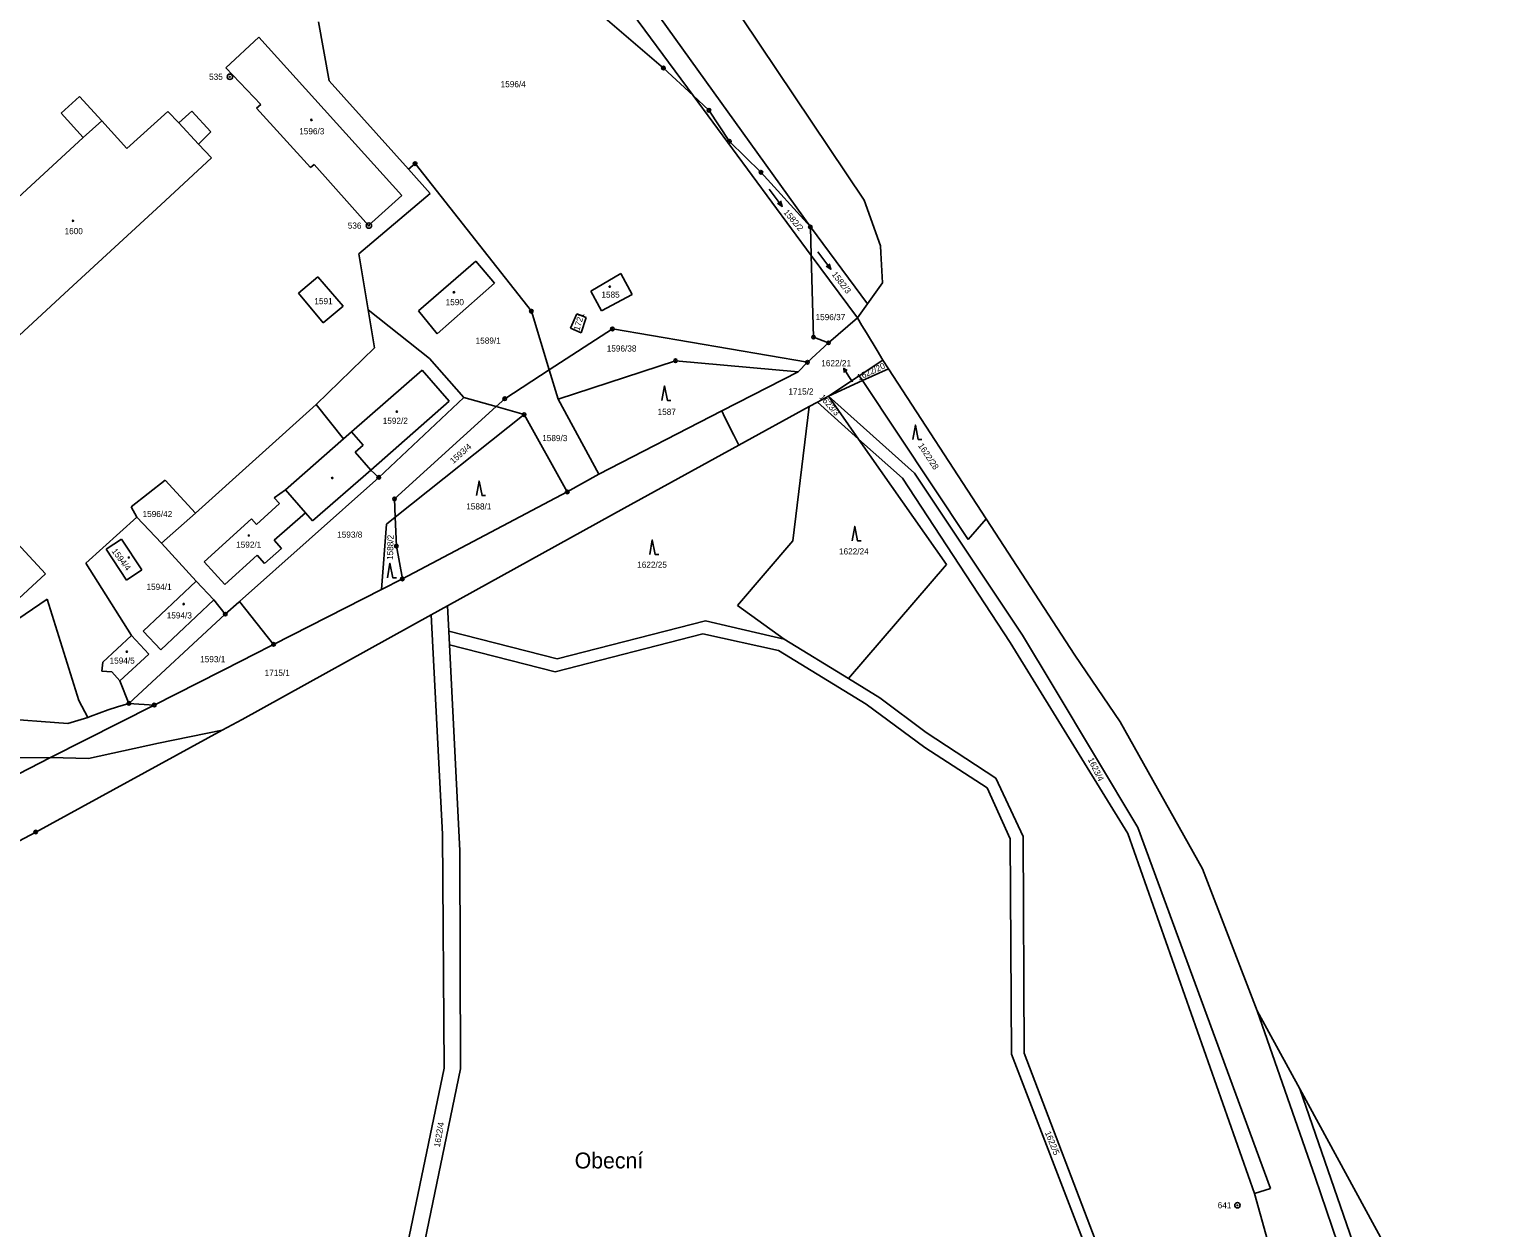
# Model space of a CAD drawing. Extents: x -763296 to -761805, y -1153670 to -1152034.
# Drawn here: x -762319 to -761910.4, y -1153075 to -1152743.4 of the extents above; entities that cross this region are included whole.
import ezdxf

# ---------------------------------------------------------------- set-up
doc = ezdxf.new("R2010")
doc.units = 0
for name, color, linetype in [('Vrstva 1', 7, 'Continuous'), ('Vrstva 13', 7, 'Continuous'), ('Vrstva 15', 7, 'Continuous'), ('Vrstva 16', 7, 'Continuous'), ('Vrstva 17', 7, 'Continuous'), ('Vrstva 18', 7, 'Continuous'), ('Vrstva 19', 7, 'Continuous'), ('Vrstva 24', 7, 'Continuous'), ('Vrstva 25', 7, 'Continuous'), ('Vrstva 4', 7, 'Continuous'), ('Vrstva 6', 7, 'Continuous')]:
    doc.layers.add(name, color=color, linetype=linetype)

msp = doc.modelspace()

# ---------------------------------------------------------------- linework, layer by layer
at = {"layer": 'Vrstva 1'}
for p, q in [((-762153.61, -1152727.41), (-762102.96, -1152798.06)), ((-762158.28, -1152730.66), (-762135.37, -1152761.7)), ((-762159.73, -1152740.22), (-762143.61, -1152754.05)), ((-762239.03, -1152741.3), (-762236.07, -1152757.56)), ((-762264.7, -1152753.98), (-762255.56, -1152745.49)), ((-762255.56, -1152745.49), (-762216.02, -1152789.32)), ((-762255.03, -1152764.19), (-762264.7, -1152753.98)), ((-762236.07, -1152757.56), (-762214.17, -1152782.08)), ((-762143.61, -1152754.05), (-762135.37, -1152761.7)), ((-762135.37, -1152761.7), (-762102.74, -1152805.92)), ((-762135.37, -1152761.7), (-762131.02, -1152765.74)), ((-762310.21, -1152766.54), (-762305.16, -1152761.92)), ((-762305.16, -1152761.92), (-762299.02, -1152768.64)), ((-762256.22, -1152765.2), (-762255.03, -1152764.19)), ((-762241.3, -1152781.61), (-762256.22, -1152765.2)), ((-762131.02, -1152765.74), (-762125.33, -1152774.37)), ((-762304.18, -1152773.27), (-762310.21, -1152766.54)), ((-762299.02, -1152768.64), (-762292.11, -1152776.34)), ((-762292.11, -1152776.34), (-762280.72, -1152766.12)), ((-762280.72, -1152766.12), (-762277.7, -1152769.18)), ((-762274.95, -1152766.7), (-762277.7, -1152769.18)), ((-762274.13, -1152765.96), (-762274.95, -1152766.7)), ((-762268.82, -1152771.72), (-762274.13, -1152765.96)), ((-762323.47, -1152791.06), (-762304.18, -1152773.27)), ((-762268.82, -1152771.72), (-762272.27, -1152775.13)), ((-762272.27, -1152775.13), (-762268.68, -1152778.96)), ((-762125.33, -1152774.37), (-762116.63, -1152782.92)), ((-762282.7, -1152791.88), (-762268.68, -1152778.96)), ((-762240.27, -1152780.76), (-762241.3, -1152781.61)), ((-762225.25, -1152797.65), (-762240.27, -1152780.76)), ((-762212.32, -1152780.52), (-762214.17, -1152782.08)), ((-762214.17, -1152782.08), (-762208.16, -1152788.81)), ((-762212.32, -1152780.52), (-762180.16, -1152821.37)), ((-762116.63, -1152782.92), (-762102.96, -1152798.06)), ((-762208.16, -1152788.81), (-762227.91, -1152805.52)), ((-762216.02, -1152789.32), (-762225.25, -1152797.65)), ((-762308.09, -1152815.37), (-762282.7, -1152791.88)), ((-762102.96, -1152798.06), (-762087.16, -1152819.32)), ((-762102.96, -1152798.06), (-762102.74, -1152805.92)), ((-762227.91, -1152805.52), (-762225.32, -1152820.97)), ((-762102.74, -1152805.92), (-762089.96, -1152823.23)), ((-762102.74, -1152805.92), (-762102.09, -1152828.56)), ((-762211.4, -1152821.24), (-762195.55, -1152807.54)), ((-762195.55, -1152807.54), (-762190.33, -1152813.6)), ((-762244.61, -1152816.37), (-762239.21, -1152811.85)), ((-762239.21, -1152811.85), (-762232.21, -1152820)), ((-762190.33, -1152813.6), (-762206.22, -1152827.59)), ((-762163.73, -1152815.82), (-762155.4, -1152810.91)), ((-762155.4, -1152810.91), (-762152.22, -1152816.74)), ((-762333.07, -1152838.41), (-762308.09, -1152815.37)), ((-762237.74, -1152824.61), (-762244.61, -1152816.37)), ((-762160.74, -1152821.29), (-762163.73, -1152815.82)), ((-762152.22, -1152816.74), (-762160.74, -1152821.29)), ((-762232.21, -1152820), (-762237.74, -1152824.61)), ((-762225.32, -1152820.97), (-762223.54, -1152831.54)), ((-762225.32, -1152820.97), (-762208.31, -1152834.45)), ((-762206.22, -1152827.59), (-762211.4, -1152821.24)), ((-762180.16, -1152821.37), (-762175.2, -1152837.62)), ((-762169.33, -1152826.08), (-762167.59, -1152822.14)), ((-762167.59, -1152822.14), (-762165.03, -1152823.1)), ((-762157.73, -1152826.28), (-762175.2, -1152837.62)), ((-762166.37, -1152827.34), (-762169.33, -1152826.08)), ((-762165.03, -1152823.1), (-762166.37, -1152827.34)), ((-762103.76, -1152835.51), (-762157.73, -1152826.28)), ((-762097.94, -1152830.12), (-762089.96, -1152823.23)), ((-762097.94, -1152830.12), (-762103.76, -1152835.51)), ((-762102.09, -1152828.56), (-762097.94, -1152830.12)), ((-762223.54, -1152831.54), (-762239.65, -1152847.2)), ((-762208.31, -1152834.45), (-762198.88, -1152845.22)), ((-762172.73, -1152845.71), (-762140.27, -1152835.1)), ((-762140.27, -1152835.1), (-762106.32, -1152838.12)), ((-762089.43, -1152839.22), (-762082.89, -1152834.96)), ((-762175.2, -1152837.62), (-762187.52, -1152845.62)), ((-762175.2, -1152837.62), (-762172.73, -1152845.71)), ((-762106.32, -1152838.12), (-762127.49, -1152848.96)), ((-762106.32, -1152838.12), (-762103.76, -1152835.51)), ((-762097.92, -1152844.88), (-762089.43, -1152839.22)), ((-762089.43, -1152839.22), (-762088.51, -1152840.59)), ((-762088.51, -1152840.59), (-762081.34, -1152837.33)), ((-762097.92, -1152844.88), (-762088.51, -1152840.59)), ((-762239.65, -1152847.2), (-762273.08, -1152877.27)), ((-762232.09, -1152856.7), (-762239.65, -1152847.2)), ((-762222.38, -1152867.36), (-762198.88, -1152845.22)), ((-762189.89, -1152847.78), (-762198.88, -1152845.22)), ((-762187.52, -1152845.62), (-762189.89, -1152847.78)), ((-762172.73, -1152845.71), (-762161.45, -1152866.45)), ((-762103.25, -1152847.78), (-762101.01, -1152846.56)), ((-762101.01, -1152846.56), (-762097.92, -1152844.88)), ((-762089.61, -1152856.76), (-762101.01, -1152846.56)), ((-762074.14, -1152866.25), (-762097.92, -1152844.88)), ((-762189.89, -1152847.78), (-762218.02, -1152873.34)), ((-762182.15, -1152849.98), (-762217.82, -1152878.43)), ((-762182.15, -1152849.98), (-762189.89, -1152847.78)), ((-762170.21, -1152871.4), (-762182.15, -1152849.98)), ((-762161.45, -1152866.45), (-762127.49, -1152848.96)), ((-762127.49, -1152848.96), (-762126.58, -1152850.78)), ((-762126.58, -1152850.78), (-762124.13, -1152855.66)), ((-762122.76, -1152858.41), (-762103.25, -1152847.78)), ((-762232.09, -1152856.7), (-762229.91, -1152854.79)), ((-762229.91, -1152854.79), (-762226.66, -1152858.5)), ((-762124.13, -1152855.66), (-762122.76, -1152858.41)), ((-762226.66, -1152858.5), (-762228.92, -1152860.41)), ((-762122.76, -1152858.41), (-762154.45, -1152875.89)), ((-762077.49, -1152867.6), (-762089.61, -1152856.76)), ((-762228.92, -1152860.41), (-762224.6, -1152865.34)), ((-762222.38, -1152867.36), (-762260.93, -1152901.73)), ((-762224.6, -1152865.34), (-762222.38, -1152867.36)), ((-762161.45, -1152866.45), (-762170.21, -1152871.4)), ((-762077.49, -1152867.6), (-762047.66, -1152913.09)), ((-762074.14, -1152866.25), (-762044.29, -1152911.05)), ((-762281.47, -1152868.16), (-762290.91, -1152875.48)), ((-762273.08, -1152877.27), (-762281.47, -1152868.16)), ((-762215.84, -1152895.47), (-762170.21, -1152871.4)), ((-762290.91, -1152875.48), (-762289.28, -1152878.4)), ((-762218.02, -1152873.34), (-762217.82, -1152878.43)), ((-762203.35, -1152902.95), (-762154.45, -1152875.89)), ((-762329.04, -1152878.48), (-762314.62, -1152894.05)), ((-762289.28, -1152878.4), (-762303.44, -1152891.15)), ((-762282.5, -1152885.56), (-762289.28, -1152878.4)), ((-762273.08, -1152877.27), (-762282.5, -1152885.56)), ((-762217.82, -1152878.43), (-762220.23, -1152880.35)), ((-762217.82, -1152878.43), (-762217.51, -1152886.39)), ((-762220.23, -1152880.35), (-762221.58, -1152898.39)), ((-762297.84, -1152887.22), (-762293.59, -1152884.52)), ((-762292.2, -1152895.79), (-762297.84, -1152887.22)), ((-762293.59, -1152884.52), (-762287.93, -1152892.99)), ((-762282.5, -1152885.56), (-762272.88, -1152896.12)), ((-762217.51, -1152886.39), (-762215.84, -1152895.47)), ((-762303.44, -1152891.15), (-762290.78, -1152911.18)), ((-762314.62, -1152894.05), (-762328.32, -1152906.75)), ((-762287.93, -1152892.99), (-762292.2, -1152895.79)), ((-762287.53, -1152909.96), (-762272.88, -1152896.12)), ((-762272.88, -1152896.12), (-762268.04, -1152901.24)), ((-762215.84, -1152895.47), (-762221.58, -1152898.39)), ((-762251.48, -1152913.6), (-762221.58, -1152898.39)), ((-762342.77, -1152920.57), (-762314.13, -1152901.12)), ((-762314.13, -1152901.12), (-762305.37, -1152929.14)), ((-762268.04, -1152901.24), (-762282.68, -1152915.08)), ((-762264.86, -1152905.24), (-762268.04, -1152901.24)), ((-762261.13, -1152901.91), (-762264.86, -1152905.24)), ((-762260.93, -1152901.73), (-762261.13, -1152901.91)), ((-762260.93, -1152901.73), (-762251.48, -1152913.6)), ((-762207.88, -1152905.46), (-762203.35, -1152902.95)), ((-762202.98, -1152909.99), (-762203.35, -1152902.95)), ((-762291.5, -1152929.93), (-762264.86, -1152905.24)), ((-762260.21, -1152934.42), (-762207.88, -1152905.46)), ((-762204.72, -1152966.18), (-762207.88, -1152905.46)), ((-762132.01, -1152907.12), (-762173.02, -1152917.64)), ((-762132.01, -1152907.12), (-762124.89, -1152908.75)), ((-762124.89, -1152908.75), (-762110.17, -1152912.13)), ((-762290.78, -1152911.18), (-762298.73, -1152918.51)), ((-762290.78, -1152911.18), (-762286.03, -1152916.33)), ((-762282.68, -1152915.08), (-762287.53, -1152909.96)), ((-762173.02, -1152917.64), (-762202.98, -1152909.99)), ((-762202.78, -1152913.76), (-762202.98, -1152909.99)), ((-762132.7, -1152910.67), (-762173.56, -1152921.2)), ((-762111.82, -1152915.34), (-762132.7, -1152910.67)), ((-762110.17, -1152912.13), (-762092.41, -1152923.08)), ((-762044.29, -1152911.05), (-762035.82, -1152925.17)), ((-762286.03, -1152916.33), (-762293.98, -1152923.65)), ((-762257.31, -1152916.57), (-762260, -1152917.94)), ((-762257.31, -1152916.57), (-762251.48, -1152913.6)), ((-762173.56, -1152921.2), (-762202.78, -1152913.76)), ((-762199.93, -1152970.65), (-762202.78, -1152913.76)), ((-762087.5, -1152930.15), (-762111.82, -1152915.34)), ((-762047.66, -1152913.09), (-762015.15, -1152965.96)), ((-762298.73, -1152918.51), (-762298.97, -1152921)), ((-762296.25, -1152921.19), (-762298.97, -1152921)), ((-762260, -1152917.94), (-762284.5, -1152930.4)), ((-762293.98, -1152923.65), (-762296.25, -1152921.19)), ((-762291.5, -1152929.93), (-762293.98, -1152923.65)), ((-762092.41, -1152923.08), (-762083.78, -1152928.41)), ((-762035.82, -1152925.17), (-762012.33, -1152964.32)), ((-762305.37, -1152929.14), (-762302.89, -1152933.84)), ((-762083.78, -1152928.41), (-762070.89, -1152937.95)), ((-762308.45, -1152935.46), (-762350.49, -1152932.38)), ((-762313.17, -1152944.94), (-762284.5, -1152930.4)), ((-762297.22, -1152931.76), (-762302.18, -1152933.54)), ((-762294.62, -1152930.91), (-762297.22, -1152931.76)), ((-762291.5, -1152929.93), (-762294.62, -1152930.91)), ((-762284.5, -1152930.4), (-762291.5, -1152929.93)), ((-762071.3, -1152942.12), (-762087.5, -1152930.15)), ((-762265.69, -1152937.38), (-762317.29, -1152965.54)), ((-762302.89, -1152933.84), (-762308.45, -1152935.46)), ((-762302.18, -1152933.54), (-762302.89, -1152933.84)), ((-762260.21, -1152934.42), (-762265.69, -1152937.38)), ((-762070.89, -1152937.95), (-762051.6, -1152950.67)), ((-762330.53, -1152953.77), (-762313.17, -1152944.94)), ((-762054.06, -1152953.34), (-762071.3, -1152942.12)), ((-762047.64, -1152967.43), (-762054.06, -1152953.34)), ((-762051.6, -1152950.67), (-762044.08, -1152966.81)), ((-762332.73, -1152973.78), (-762317.29, -1152965.54)), ((-761980.07, -1153065.61), (-762015.15, -1152965.96)), ((-762012.33, -1152964.32), (-761975.69, -1153064.2)), ((-762204.72, -1152966.18), (-762204.29, -1153030.96)), ((-762047.64, -1152967.43), (-762047.28, -1153027.01)), ((-762044.08, -1152966.81), (-762043.84, -1153026.77)), ((-762199.93, -1152970.65), (-762199.78, -1153031.1)), ((-761979.29, -1153015), (-761963.26, -1153061.05)), ((-762047.28, -1153027.01), (-762008.04, -1153129.14)), ((-762043.84, -1153026.77), (-762005.01, -1153128.52)), ((-762204.29, -1153030.96), (-762227.78, -1153143.46)), ((-762223.14, -1153143.92), (-762199.78, -1153031.1)), ((-761936.63, -1153125.95), (-761967.52, -1153036.66)), ((-761963.26, -1153061.05), (-761942.08, -1153123.55)), ((-761975.69, -1153064.2), (-761980.07, -1153065.61)), ((-761973.25, -1153089.91), (-761980.07, -1153065.61))]:
    msp.add_line(p, q, dxfattribs=at)
at = {"layer": 'Vrstva 13'}
for p, q in [((-762121.93, -1152740.13), (-762088.07, -1152790.67)), ((-762088.07, -1152790.67), (-762083.58, -1152803.27)), ((-762083.58, -1152803.27), (-762083.44, -1152805.2)), ((-762083.44, -1152805.2), (-762083.02, -1152813.56)), ((-762087.16, -1152819.32), (-762083.02, -1152813.56)), ((-762089.96, -1152823.23), (-762087.16, -1152819.32)), ((-762088.7, -1152825.32), (-762089.96, -1152823.23)), ((-762087.47, -1152827.36), (-762088.7, -1152825.32)), ((-762084.51, -1152832.28), (-762087.47, -1152827.36)), ((-762082.89, -1152834.96), (-762084.51, -1152832.28)), ((-762081.34, -1152837.33), (-762082.89, -1152834.96)), ((-762081.34, -1152837.33), (-762054.35, -1152878.82)), ((-762054.35, -1152878.82), (-762029.76, -1152916.6)), ((-762029.76, -1152916.6), (-762021.97, -1152928.1)), ((-762021.97, -1152928.1), (-762017.26, -1152935.05)), ((-761994.5, -1152975.74), (-762017.26, -1152935.05)), ((-761979.29, -1153015), (-761994.5, -1152975.74)), ((-761979.29, -1153015), (-761967.52, -1153036.66)), ((-761910.36, -1153141.85), (-761967.52, -1153036.66))]:
    msp.add_line(p, q, dxfattribs=at)
at = {"layer": 'Vrstva 16'}
for p in [(-762093.719, -1152837.208), (-762091.34, -1152840.96)]:
    msp.add_line(p, (-762092.11, -1152839.74), dxfattribs=at)
msp.add_lwpolyline([(-762093.605, -1152838.32), (-762093.719, -1152837.208), (-762092.76, -1152837.784)], dxfattribs=at)
at = {"layer": 'Vrstva 24'}
for centre, radius in [((-762263.57, -1152756.47), 0.75), ((-762263.57, -1152756.47), 0.1), ((-762143.61, -1152754.05), 0.5), ((-762143.61, -1152754.05), 0.1), ((-762131.02, -1152765.74), 0.5), ((-762131.02, -1152765.74), 0.1), ((-762125.33, -1152774.37), 0.5), ((-762125.33, -1152774.37), 0.1), ((-762212.32, -1152780.52), 0.5), ((-762212.32, -1152780.52), 0.1), ((-762116.63, -1152782.92), 0.5), ((-762116.63, -1152782.92), 0.1), ((-762225.1, -1152797.67), 0.75), ((-762225.1, -1152797.67), 0.1), ((-762102.96, -1152798.06), 0.5), ((-762102.96, -1152798.06), 0.1), ((-762180.16, -1152821.37), 0.5), ((-762180.16, -1152821.37), 0.1), ((-762157.73, -1152826.28), 0.5), ((-762157.73, -1152826.28), 0.1), ((-762102.09, -1152828.56), 0.5), ((-762102.09, -1152828.56), 0.1), ((-762097.94, -1152830.12), 0.5), ((-762097.94, -1152830.12), 0.1), ((-762140.27, -1152835.1), 0.5), ((-762140.27, -1152835.1), 0.1), ((-762103.76, -1152835.51), 0.5), ((-762103.76, -1152835.51), 0.1), ((-762187.52, -1152845.62), 0.5), ((-762187.52, -1152845.62), 0.1), ((-762182.15, -1152849.98), 0.5), ((-762182.15, -1152849.98), 0.1), ((-762222.38, -1152867.36), 0.5), ((-762222.38, -1152867.36), 0.1), ((-762170.21, -1152871.4), 0.5), ((-762170.21, -1152871.4), 0.1), ((-762218.02, -1152873.34), 0.5), ((-762218.02, -1152873.34), 0.1), ((-762217.51, -1152886.39), 0.5), ((-762217.51, -1152886.39), 0.1), ((-762215.84, -1152895.47), 0.5), ((-762215.84, -1152895.47), 0.1), ((-762264.86, -1152905.24), 0.5), ((-762264.86, -1152905.24), 0.1), ((-762251.48, -1152913.6), 0.5), ((-762251.48, -1152913.6), 0.1), ((-762291.5, -1152929.93), 0.5), ((-762291.5, -1152929.93), 0.1), ((-762284.5, -1152930.4), 0.5), ((-762284.5, -1152930.4), 0.1), ((-762317.29, -1152965.54), 0.5), ((-762317.29, -1152965.54), 0.1), ((-761984.8, -1153068.87), 0.75), ((-761984.8, -1153068.87), 0.1)]:
    msp.add_circle(centre, radius, dxfattribs=at)
at = {"layer": 'Vrstva 25'}
for points in [[(-762114.345, -1152787.547), (-762110.755, -1152792.353), (-762111.252, -1152790.852)], [(-762110.755, -1152792.353), (-762112.053, -1152791.451)], [(-762100.865, -1152804.957), (-762097.275, -1152809.763), (-762097.772, -1152808.262)], [(-762097.275, -1152809.763), (-762098.573, -1152808.861)], [(-762144.02, -1152846.07), (-762143.32, -1152842.07), (-762142.52, -1152846.07), (-762141.52, -1152846.07)], [(-762074.61, -1152856.88), (-762073.91, -1152852.88), (-762073.11, -1152856.88), (-762072.11, -1152856.88)], [(-762195.31, -1152872.42), (-762194.61, -1152868.42), (-762193.81, -1152872.42), (-762192.81, -1152872.42)], [(-762091.39, -1152884.96), (-762090.69, -1152880.96), (-762089.89, -1152884.96), (-762088.89, -1152884.96)], [(-762147.41, -1152888.68), (-762146.71, -1152884.68), (-762145.91, -1152888.68), (-762144.91, -1152888.68)], [(-762220, -1152895.15), (-762219.3, -1152891.15), (-762218.5, -1152895.15), (-762217.5, -1152895.15)]]:
    msp.add_lwpolyline(points, dxfattribs=at)
for centre in [(-762241.01, -1152768.42), (-762306.97, -1152796.34), (-762158.46, -1152814.58), (-762201.58, -1152816.13), (-762217.39, -1152849.15), (-762235.25, -1152867.55), (-762258.32, -1152883.46), (-762291.52, -1152889.55), (-762276.35, -1152902.44), (-762292.08, -1152915.65)]:
    msp.add_circle(centre, 0.175, dxfattribs=at)
at = {"layer": 'Vrstva 4'}
for p, q in [((-762304.18, -1152773.27), (-762299.02, -1152768.64)), ((-762277.7, -1152769.18), (-762272.27, -1152775.13)), ((-762229.91, -1152854.79), (-762210.41, -1152837.69)), ((-762210.41, -1152837.69), (-762202.87, -1152846.29)), ((-762202.87, -1152846.29), (-762224.6, -1152865.34)), ((-762248.22, -1152870.84), (-762232.09, -1152856.7)), ((-762224.6, -1152865.34), (-762240.68, -1152879.44)), ((-762251.27, -1152873.06), (-762248.22, -1152870.84)), ((-762248.22, -1152870.84), (-762242.66, -1152877.18)), ((-762256.18, -1152880.43), (-762249.83, -1152874.64)), ((-762249.83, -1152874.64), (-762251.27, -1152873.06)), ((-762270.65, -1152890.75), (-762257.62, -1152878.86)), ((-762257.62, -1152878.86), (-762256.18, -1152880.43)), ((-762251.29, -1152884.74), (-762242.66, -1152877.18)), ((-762242.66, -1152877.18), (-762240.68, -1152879.44)), ((-762253.96, -1152891.19), (-762249.25, -1152887.07)), ((-762249.25, -1152887.07), (-762251.29, -1152884.74)), ((-762264.92, -1152897.03), (-762270.65, -1152890.75)), ((-762264.92, -1152897.03), (-762255.98, -1152888.88)), ((-762255.98, -1152888.88), (-762253.96, -1152891.19))]:
    msp.add_line(p, q, dxfattribs=at)
at = {"layer": 'Vrstva 6'}
for p, q in [((-762088.51, -1152840.59), (-762059.32, -1152884.57)), ((-762089.61, -1152856.76), (-762097.92, -1152844.88)), ((-762103.25, -1152847.78), (-762107.82, -1152884.96)), ((-762065.3, -1152891.5), (-762089.61, -1152856.76)), ((-762059.32, -1152884.57), (-762054.35, -1152878.82)), ((-762107.82, -1152884.96), (-762123.11, -1152902.83)), ((-762092.41, -1152923.08), (-762065.3, -1152891.5)), ((-762123.11, -1152902.83), (-762110.17, -1152912.13)), ((-762283.31, -1152940.94), (-762265.69, -1152937.38)), ((-762302.73, -1152945.15), (-762283.31, -1152940.94)), ((-762342.03, -1152945.09), (-762313.17, -1152944.94)), ((-762313.17, -1152944.94), (-762302.73, -1152945.15))]:
    msp.add_line(p, q, dxfattribs=at)

# ---------------------------------------------------------------- texts
at = {"layer": 'Vrstva 15'}
msp.add_text('Obecní', height=4.4, dxfattribs=at).set_placement((-762168.167, -1153058.68))
at = {"layer": 'Vrstva 16'}
msp.add_text('1622/21', height=1.7, dxfattribs=at).set_placement((-762099.931, -1152836.6))
at = {"layer": 'Vrstva 17'}
for s, p in [('535', (-762269.324, -1152757.32)), ('536', (-762230.947, -1152798.52)), ('641', (-761990.246, -1153069.72))]:
    msp.add_text(s, height=1.7, dxfattribs=at).set_placement(p)
at = {"layer": 'Vrstva 18'}
for s, height, p in [('1596/4', 1.7, (-762188.651, -1152759.37)), ('1591', 1.7, (-762240.194, -1152819.43)), ('1596/37', 1.7, (-762101.517, -1152823.85)), ('1589/1', 1.7, (-762195.57, -1152830.36)), ('1596/38', 1.7, (-762159.298, -1152832.54)), ('1715/2', 1.7, (-762109.037, -1152844.45)), ('1622/21', 0.1, (-762091.595, -1152840.96)), ('1587', 1.7, (-762145.219, -1152850.08)), ('1589/3', 1.7, (-762177.145, -1152857.34)), ('1588/1', 1.7, (-762198.167, -1152876.26)), ('1596/42', 1.7, (-762287.724, -1152878.36)), ('1593/8', 1.7, (-762233.878, -1152884.07)), ('1622/24', 1.7, (-762095.035, -1152888.71)), ('1622/25', 1.7, (-762150.872, -1152892.39)), ('1594/1', 1.7, (-762286.643, -1152898.52)), ('1593/1', 1.7, (-762271.79, -1152918.55)), ('1715/1', 1.7, (-762253.947, -1152922.32))]:
    msp.add_text(s, height=height, dxfattribs=at).set_placement(p)
for s, rotation, p in [('1582/2', 310.37124, (-762110.498, -1152794.086)), ('1582/3', 307.67834, (-762097.15, -1152811.197)), ('1721', 73.16671, (-762166.884, -1152826.906)), ('1622/20', 24.92366, (-762089.543, -1152840.555)), ('1623/3', 311.91823, (-762100.587, -1152845.297)), ('1593/4', 41.76862, (-762201.745, -1152863.723)), ('1622/28', 303.43845, (-762073.233, -1152858.584)), ('1588/2', 88.63657, (-762218.434, -1152890.257)), ('1623/4', 296.10459, (-762026.241, -1152945.446)), ('1622/4', 80.0995, (-762205.484, -1153052.893)), ('1622/5', 292.15118, (-762038.116, -1153048.744))]:
    msp.add_text(s, height=1.7, rotation=rotation, dxfattribs=at).set_placement(p)
at = {"layer": 'Vrstva 19'}
for s, p in [('1596/3', (-762244.378, -1152772.4)), ('1600', (-762309.309, -1152800.05)), ('1590', (-762203.869, -1152819.71)), ('1585', (-762160.776, -1152817.63)), ('1592/2', (-762221.279, -1152852.55)), ('1592/1', (-762261.837, -1152886.85)), ('1594/3', (-762281.038, -1152906.43)), ('1594/5', (-762296.848, -1152918.94))]:
    msp.add_text(s, height=1.7, dxfattribs=at).set_placement(p)
msp.add_text('1594/4', height=1.7, rotation=306.99079, dxfattribs=at).set_placement((-762296.359, -1152887.818))

doc.saveas('drawing.dxf')
